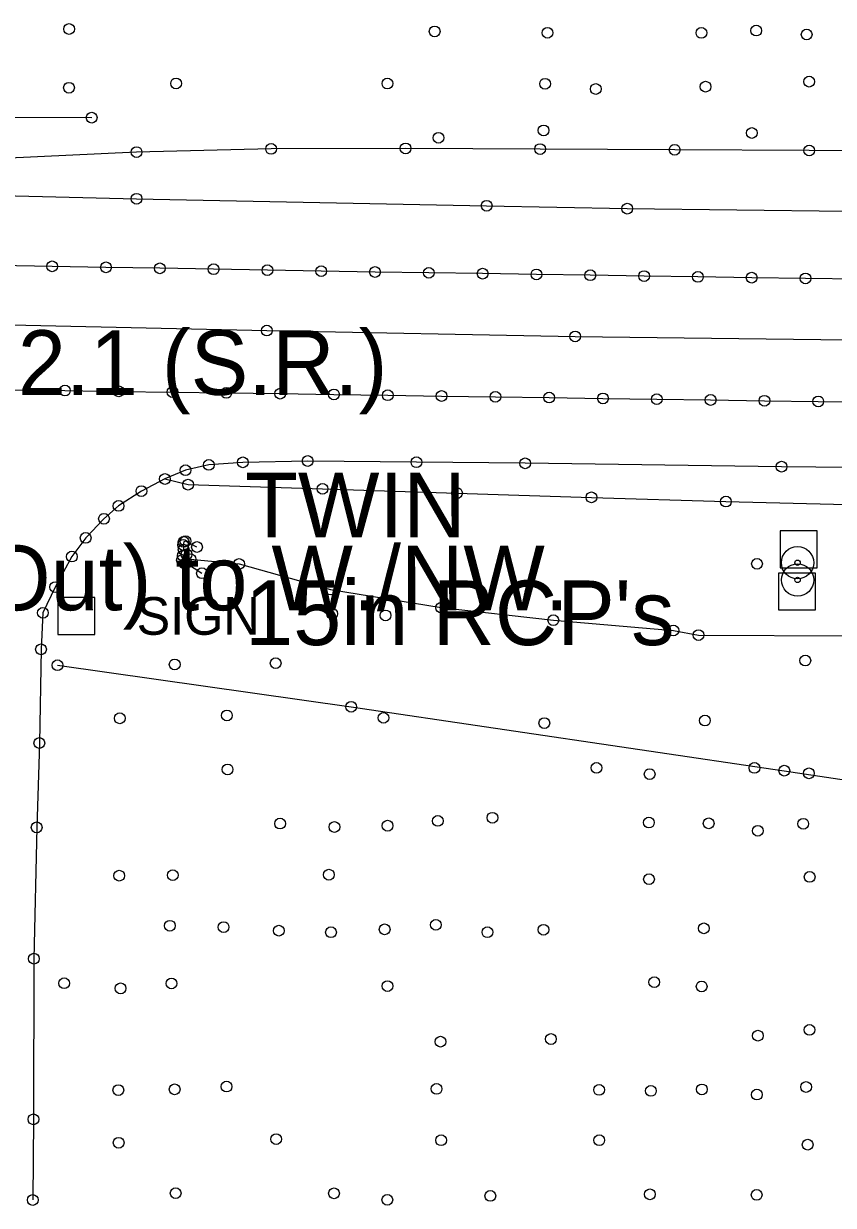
# Model space of a CAD drawing. Extents: x 20503438 to 20508873, y 7964251 to 7984667.
# Drawn here: x 20505557.5 to 20505708, y 7970387.8 to 7970607.3 of the extents above; entities that cross this region are included whole.
import ezdxf

# ---------------------------------------------------------------- set-up
doc = ezdxf.new("R2010")
doc.units = 0
for name, color, linetype in [('SurBreakLine', 7, 'Continuous'), ('SurConcreteSlab', 7, 'Continuous'), ('SurDrainageArrowUp', 7, 'Continuous'), ('SurEdgeRoadPaved', 7, 'Continuous'), ('SurEdgeShoulderPaved', 7, 'Continuous'), ('SurEdgeShoulderUnpaved', 7, 'Continuous'), ('SurFenceChainLink', 7, 'Continuous'), ('SurPointsNonDTM', 7, 'Continuous'), ('SurRoadPoints', 7, 'Continuous'), ('SurSurveyPoints', 7, 'Continuous'), ('SurTxtDrainage', 7, 'Continuous')]:
    doc.layers.add(name, color=color, linetype=linetype)

msp = doc.modelspace()

# ---------------------------------------------------------------- linework, layer by layer
at = {"layer": 'SurBreakLine'}
for points in [[(20504771.9, 7970563.37), (20504797.86, 7970563), (20504843.99, 7970562.34), (20504867.04, 7970562.01), (20505027.11, 7970559.46), (20505056.57, 7970559.02), (20505122.33, 7970557.99), (20505134.3, 7970557.78), (20505181.34, 7970557.02), (20505190.04, 7970556.88), (20505298.19, 7970555.19), (20505381.79, 7970553.77), (20505481.65, 7970551.95), (20505538.21, 7970551.74), (20505602.69, 7970550.28), (20505659.98, 7970549.19), (20505725.91, 7970548.38)], [(20505589.71, 7970510.09), (20505587.59, 7970511.17), (20505587.24, 7970511.05), (20505587.15, 7970510.47), (20505587.23, 7970509.59), (20505587.78, 7970508.72), (20505587.1, 7970508.47), (20505586.93, 7970507.67), (20505587.47, 7970506.97), (20505587.76, 7970507.09), (20505590.64, 7970505.21)]]:
    msp.add_lwpolyline(points, dxfattribs=at)
at = {"layer": 'SurConcreteSlab'}
for points in [[(20505712.78, 7970559.82), (20505702.78, 7970559.97), (20505692.78, 7970560.11), (20505682.79, 7970560.26), (20505672.79, 7970560.41), (20505662.79, 7970560.56), (20505652.79, 7970560.71), (20505642.79, 7970560.86), (20505632.79, 7970561.01), (20505622.79, 7970561.16), (20505612.79, 7970561.32), (20505602.79, 7970561.5), (20505592.8, 7970561.68), (20505582.8, 7970561.85), (20505572.8, 7970562.03), (20505562.8, 7970562.21), (20505552.8, 7970562.39), (20505542.8, 7970562.57), (20505532.81, 7970562.75), (20505522.81, 7970562.93), (20505515.54, 7970563.06)], [(20505515.18, 7970539.88), (20505525.17, 7970539.73), (20505535.17, 7970539.59), (20505545.17, 7970539.44), (20505555.17, 7970539.3), (20505565.17, 7970539.15), (20505575.17, 7970539), (20505585.16, 7970538.86), (20505595.16, 7970538.71), (20505605.16, 7970538.57), (20505615.16, 7970538.42), (20505625.16, 7970538.27), (20505635.16, 7970538.13), (20505645.16, 7970537.98), (20505655.15, 7970537.84), (20505665.15, 7970537.69), (20505675.15, 7970537.55), (20505685.15, 7970537.4), (20505695.15, 7970537.25), (20505705.15, 7970537.12), (20505715.14, 7970537)], [(20505559.92, 7970458.02), (20505559.41, 7970433.63), (20505559.32, 7970403.8), (20505559.19, 7970388.82)]]:
    msp.add_lwpolyline(points, dxfattribs=at)
at = {"layer": 'SurDrainageArrowUp'}
for points in [[(20505509.27, 7970583.65), (20505510.79, 7970583.61), (20505512.44, 7970584.29), (20505514.65, 7970584.86), (20505521.9, 7970588.08), (20505529.65, 7970588.65), (20505549.4, 7970589.9), (20505570.14, 7970589.83)], [(20505588.51, 7970507.81), (20505597.53, 7970506.94), (20505614.51, 7970502.19), (20505635.08, 7970498.83), (20505655.93, 7970496.49), (20505678.23, 7970494.58), (20505682.9, 7970493.73), (20505711.11, 7970493.62), (20505731.16, 7970493.62), (20505757.46, 7970492.01), (20505802.13, 7970488.46), (20505848.74, 7970485.55), (20505856.14, 7970483.32), (20505901.79, 7970481.39), (20505945.72, 7970472.48), (20505988.92, 7970467.48), (20505998.29, 7970466.36)]]:
    msp.add_lwpolyline(points, dxfattribs=at)
at = {"layer": 'SurEdgeRoadPaved'}
msp.add_lwpolyline([(20505535.9, 7970575.81), (20505578.48, 7970574.77), (20505643.53, 7970573.47), (20505669.66, 7970572.93), (20505730.8, 7970572.24)], dxfattribs=at)
at = {"layer": 'SurEdgeShoulderPaved'}
msp.add_lwpolyline([(20505723.75, 7970524.74), (20505698.34, 7970525.01), (20505650.69, 7970525.63), (20505630.49, 7970525.84), (20505610.28, 7970526.06), (20505598.23, 7970525.81), (20505591.91, 7970525.33), (20505587.57, 7970524.35), (20505583.75, 7970522.72), (20505579.38, 7970520.47), (20505575.14, 7970517.72), (20505572.43, 7970515.33), (20505569.03, 7970511.78), (20505566.46, 7970508.31), (20505563.37, 7970502.65), (20505561.08, 7970497.86), (20505560.73, 7970491.09), (20505560.42, 7970473.69), (20505559.92, 7970458.02)], dxfattribs=at)
at = {"layer": 'SurEdgeShoulderUnpaved'}
for points in [[(20506013.34, 7970576.96), (20506003.27, 7970578.4), (20505978.34, 7970579.89), (20505953.4, 7970581.38), (20505928.43, 7970582.06), (20505903.43, 7970582.24), (20505878.44, 7970582.42), (20505853.45, 7970582.6), (20505828.45, 7970582.79), (20505803.45, 7970582.99), (20505778.46, 7970583.18), (20505753.46, 7970583.38), (20505728.47, 7970583.57), (20505703.47, 7970583.73), (20505678.47, 7970583.86), (20505653.47, 7970583.99), (20505628.47, 7970584.12), (20505603.48, 7970584.03), (20505578.48, 7970583.43), (20505553.53, 7970582.26), (20505528.79, 7970578.89), (20505515.58, 7970576.01)], [(20505583.75, 7970522.72), (20505588.05, 7970521.67), (20505613.04, 7970520.89), (20505638.02, 7970520.1), (20505663.01, 7970519.31), (20505687.99, 7970518.52), (20505712.98, 7970517.9), (20505737.97, 7970517.38), (20505762.96, 7970516.86), (20505787.95, 7970516.34), (20505812.95, 7970515.82), (20505837.94, 7970515.3), (20505862.93, 7970514.78), (20505887.92, 7970514.26), (20505912.91, 7970514.05), (20505937.9, 7970513.99), (20505962.89, 7970513.93), (20505987.89, 7970513.87), (20506012.76, 7970511.67), (20506037.35, 7970507.53), (20506060.92, 7970500.21), (20506079.1, 7970483.65), (20506094.14, 7970463.86), (20506101.05, 7970448.2)]]:
    msp.add_lwpolyline(points, dxfattribs=at)
at = {"layer": 'SurFenceChainLink'}
msp.add_lwpolyline([(20505563.79, 7970488.13), (20505618.36, 7970480.42), (20505698.84, 7970468.55), (20505760.89, 7970459.22), (20505831.24, 7970448.68), (20505921.66, 7970435.36), (20506003.71, 7970422.97), (20506019.92, 7970394.05)], dxfattribs=at)
at = {"layer": 'SurPointsNonDTM'}
for centre in [(20505563.79, 7970488.13), (20505618.36, 7970480.42), (20505698.84, 7970468.55)]:
    msp.add_circle(centre, 1, dxfattribs=at)
at = {"layer": 'SurRoadPoints'}
for points in [[(20505701.52, 7970506.25), (20505701.52, 7970506.25), (20505704.95, 7970506.25), (20505704.95, 7970513.11), (20505698.09, 7970513.11), (20505698.09, 7970506.25), (20505701.52, 7970506.25)], [(20505701.21, 7970498.4), (20505701.21, 7970498.4), (20505704.64, 7970498.4), (20505704.64, 7970505.26), (20505697.78, 7970505.26), (20505697.78, 7970498.4), (20505701.21, 7970498.4)], [(20505567.28, 7970493.86), (20505567.28, 7970493.86), (20505570.71, 7970493.86), (20505570.71, 7970500.72), (20505563.85, 7970500.72), (20505563.85, 7970493.86), (20505567.28, 7970493.86)]]:
    msp.add_lwpolyline(points, dxfattribs=at)
for centre, radius in [((20505701.3, 7970507.17), 3), ((20505701.3, 7970507.17), 0.5), ((20505701.31, 7970503.97), 3), ((20505701.31, 7970503.97), 0.5)]:
    msp.add_circle(centre, radius, dxfattribs=at)
at = {"layer": 'SurSurveyPoints'}
for centre in [(20505565.94, 7970606.29), (20505633.87, 7970605.85), (20505654.84, 7970605.59), (20505683.44, 7970605.57), (20505693.62, 7970606), (20505703, 7970605.27), (20505703.46, 7970596.52), (20505565.92, 7970595.38), (20505585.82, 7970596.18), (20505625.09, 7970596.16), (20505654.39, 7970596.12), (20505663.81, 7970595.15), (20505684.21, 7970595.58), (20505570.14, 7970589.83), (20505634.59, 7970586.09), (20505654.11, 7970587.46), (20505692.81, 7970586.98), (20505578.48, 7970583.43), (20505603.48, 7970584.03), (20505628.47, 7970584.12), (20505653.47, 7970583.99), (20505678.47, 7970583.86), (20505703.47, 7970583.73), (20505578.48, 7970574.77), (20505643.53, 7970573.47), (20505669.66, 7970572.93), (20505562.8, 7970562.21), (20505572.8, 7970562.03), (20505582.8, 7970561.85), (20505592.8, 7970561.68), (20505602.79, 7970561.5), (20505612.79, 7970561.32), (20505622.79, 7970561.16), (20505632.79, 7970561.01), (20505642.79, 7970560.86), (20505652.79, 7970560.71), (20505662.79, 7970560.56), (20505672.79, 7970560.41), (20505682.79, 7970560.26), (20505692.78, 7970560.11), (20505702.78, 7970559.97), (20505602.69, 7970550.28), (20505659.98, 7970549.19), (20505565.17, 7970539.15), (20505575.17, 7970539), (20505585.16, 7970538.86), (20505595.16, 7970538.71), (20505605.16, 7970538.57), (20505615.16, 7970538.42), (20505625.16, 7970538.27), (20505635.16, 7970538.13), (20505645.16, 7970537.98), (20505655.15, 7970537.84), (20505665.15, 7970537.69), (20505675.15, 7970537.55), (20505685.15, 7970537.4), (20505695.15, 7970537.25), (20505705.15, 7970537.12), (20505587.57, 7970524.35), (20505591.91, 7970525.33), (20505598.23, 7970525.81), (20505610.28, 7970526.06), (20505630.49, 7970525.84), (20505650.69, 7970525.63), (20505698.34, 7970525.01), (20505583.75, 7970522.72), (20505579.38, 7970520.47), (20505588.05, 7970521.67), (20505613.04, 7970520.89), (20505638.02, 7970520.1), (20505575.14, 7970517.72), (20505663.01, 7970519.31), (20505687.99, 7970518.52), (20505572.43, 7970515.33), (20505569.03, 7970511.78), (20505587.24, 7970511.05), (20505587.59, 7970511.17), (20505587.15, 7970510.47), (20505587.23, 7970509.59), (20505587.78, 7970508.72), (20505589.71, 7970510.09), (20505566.46, 7970508.31), (20505586.93, 7970507.67), (20505587.1, 7970508.47), (20505587.47, 7970506.97), (20505587.76, 7970507.09), (20505588.51, 7970507.81), (20505597.53, 7970506.94), (20505693.77, 7970506.96), (20505590.64, 7970505.21), (20505563.37, 7970502.65), (20505614.51, 7970502.19), (20505561.08, 7970497.86), (20505614.81, 7970497.7), (20505635.08, 7970498.83), (20505624.75, 7970497.39), (20505655.93, 7970496.49), (20505678.23, 7970494.58), (20505682.9, 7970493.73), (20505560.73, 7970491.09), (20505702.74, 7970489), (20505585.57, 7970488.28), (20505604.33, 7970488.52), (20505575.36, 7970478.28), (20505595.27, 7970478.81), (20505624.37, 7970478.36), (20505684.09, 7970477.86), (20505654.25, 7970477.39), (20505560.42, 7970473.69), (20505663.94, 7970469.07), (20505693.29, 7970469.06), (20505595.4, 7970468.78), (20505673.83, 7970467.91), (20505703.42, 7970468.05), (20505605.15, 7970458.72), (20505615.24, 7970458.09), (20505625.13, 7970458.33), (20505634.46, 7970459.22), (20505644.61, 7970459.81), (20505673.68, 7970458.92), (20505684.79, 7970458.77), (20505702.36, 7970458.69), (20505559.92, 7970458.02), (20505559.92, 7970458.02), (20505693.92, 7970457.39), (20505575.26, 7970449.05), (20505585.21, 7970449.14), (20505614.22, 7970449.23), (20505673.7, 7970448.4), (20505703.55, 7970448.82), (20505584.67, 7970439.75), (20505594.65, 7970439.5), (20505604.92, 7970438.83), (20505614.61, 7970438.54), (20505624.58, 7970439.08), (20505634.1, 7970439.92), (20505643.68, 7970438.55), (20505654.1, 7970439.01), (20505683.89, 7970439.27), (20505559.41, 7970433.63), (20505565.03, 7970429.07), (20505575.51, 7970428.12), (20505584.97, 7970429.03), (20505625.11, 7970428.55), (20505674.68, 7970429.27), (20505683.49, 7970428.48), (20505655.48, 7970418.71), (20505693.93, 7970419.33), (20505703.52, 7970420.41), (20505634.96, 7970418.22), (20505595.2, 7970409.88), (20505702.89, 7970409.81), (20505575.1, 7970409.23), (20505585.56, 7970409.37), (20505634.22, 7970409.45), (20505664.43, 7970409.27), (20505674.05, 7970409.08), (20505683.53, 7970409.36), (20505693.75, 7970408.39), (20505559.32, 7970403.8), (20505575.16, 7970399.45), (20505604.42, 7970400.12), (20505635.07, 7970399.91), (20505664.46, 7970399.92), (20505703.19, 7970399.09), (20505585.75, 7970390.09), (20505615.17, 7970390.06), (20505559.19, 7970388.82), (20505625.08, 7970388.85), (20505644.21, 7970389.57), (20505673.87, 7970389.87), (20505693.7, 7970389.77)]:
    msp.add_circle(centre, 1, dxfattribs=at)

# ---------------------------------------------------------------- texts
at = {"layer": 'SurRoadPoints'}
msp.add_text('SIGN', height=6.995, rotation=360, dxfattribs=at).set_placement((20505578.49, 7970493.79))
at = {"layer": 'SurTxtDrainage'}
for s, p in [('Sta. 104+32.1 (S.R.)', (20505478.35, 7970538.34)), ('TWIN', (20505598.66, 7970511.87)), ('18" RCP (Out) to W./NW.', (20505478.35, 7970498.34)), ("15in RCP's", (20505598.66, 7970491.87))]:
    msp.add_text(s, height=12, dxfattribs=at).set_placement(p)

doc.saveas('drawing.dxf')
